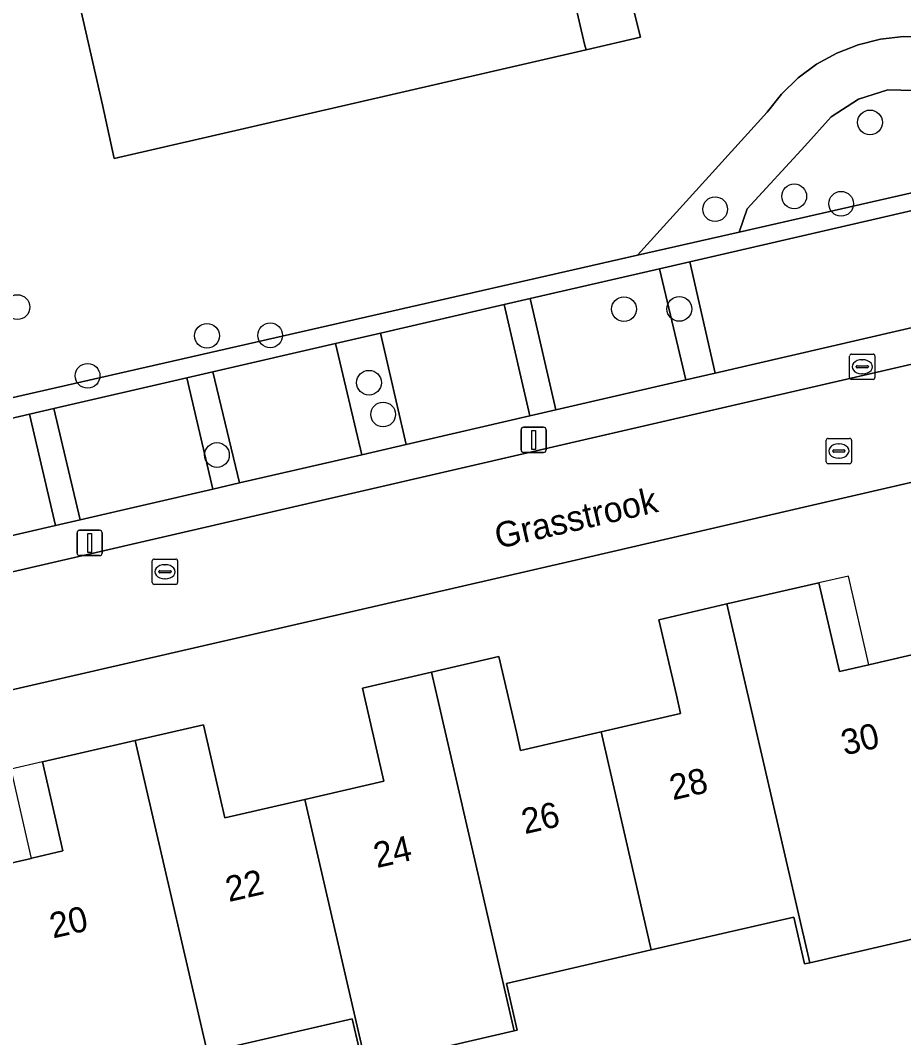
# Model space of a CAD drawing. Extents: x 156412 to 157779, y 382335 to 383768.
# Drawn here: x 156810.03 to 156844.92, y 382698.63 to 382738.81 of the extents above; entities that cross this region are included whole.
import ezdxf

# ---------------------------------------------------------------- set-up
doc = ezdxf.new("R2010")
doc.units = 0
for name, color, linetype in [('IMGEO_Boom', 7, 'Continuous'), ('IMGEO_Brandkraan', 7, 'Continuous'), ('IMGEO_Erf', 7, 'Continuous'), ('IMGEO_Groenvoorziening', 7, 'Continuous'), ('IMGEO_Haag', 7, 'Continuous'), ('IMGEO_Lichtmast', 7, 'Continuous'), ('IMGEO_Openbare_ruimte_label', 7, 'Continuous'), ('IMGEO_Pand', 7, 'Continuous'), ('IMGEO_Pand_nummerreeks', 7, 'Continuous'), ('IMGEO_Pand_overbouw', 7, 'Continuous'), ('IMGEO_Parkeervlak_open', 7, 'Continuous'), ('IMGEO_Rijbaan_lokaal_open', 7, 'Continuous'), ('IMGEO_Rioolput', 7, 'Continuous'), ('IMGEO_Voetpad_gesloten', 7, 'Continuous'), ('IMGEO_Voetpad_open', 7, 'Continuous')]:
    doc.layers.add(name, color=color, linetype=linetype)

msp = doc.modelspace()

# ---------------------------------------------------------------- linework, layer by layer
at = {"layer": 'IMGEO_Boom'}
for centre in [(156843.589, 382734.775), (156840.596, 382731.858), (156842.449, 382731.563), (156837.473, 382731.349), (156809.918, 382727.482), (156833.872, 382727.402), (156836.059, 382727.412), (156817.404, 382726.349), (156819.9, 382726.367), (156812.688, 382724.769), (156823.804, 382724.497), (156824.361, 382723.243), (156817.797, 382721.643)]:
    msp.add_circle(centre, 0.489, dxfattribs=at)
at = {"layer": 'IMGEO_Brandkraan'}
for p, q in [((156842.782, 382724.7), (156842.782, 382725.552)), ((156842.857, 382725.626), (156843.709, 382725.626)), ((156843.783, 382725.552), (156843.783, 382724.7)), ((156843.041, 382725.12), (156843.041, 382725.132)), ((156843.479, 382725.083), (156843.081, 382725.083)), ((156843.084, 382725.169), (156843.482, 382725.169)), ((156843.27, 382725.406), (156843.295, 382725.406)), ((156843.525, 382725.132), (156843.525, 382725.12)), ((156843.293, 382724.846), (156843.268, 382724.846)), ((156843.709, 382724.626), (156842.857, 382724.626))]:
    msp.add_line(p, q, dxfattribs=at)
for points in [[(156842.782, 382724.7), (156842.782, 382725.552)], [(156842.857, 382725.626), (156843.709, 382725.626)], [(156843.783, 382725.552), (156843.783, 382724.7)], [(156843.709, 382724.626), (156842.857, 382724.626)]]:
    msp.add_lwpolyline(points, dxfattribs=at)
for centre, radius, start, end in [((156842.859, 382725.55), 0.0765, 91.552, 178.448), ((156842.859, 382725.55), 0.0765, 91.552, 178.448), ((156843.707, 382725.55), 0.0765, 1.552, 88.448), ((156843.707, 382725.55), 0.0765, 1.552, 88.448), ((156843.081, 382725.129), 0.0403, 85.8775, 175.7526), ((156843.078, 382725.119), 0.0366, 178.938, 274.7102), ((156843.482, 382725.126), 0.043, 264.8664, 352.4533), ((156843.486, 382725.131), 0.0386, 1.7309, 96.639), ((156842.859, 382724.702), 0.0765, 181.552, 268.448), ((156842.859, 382724.702), 0.0765, 181.552, 268.448), ((156843.707, 382724.702), 0.0765, 271.552, 358.448), ((156843.707, 382724.702), 0.0765, 271.552, 358.448)]:
    msp.add_arc(centre, radius, start, end, dxfattribs=at)
for centre, major_axis, ratio, start_param, end_param in [((156843.269, 382725.126), (-0.387, 0.002), 0.722429, 4.712389, 7.853982), ((156843.294, 382725.126), (-0.39, 0.002), 0.717154, 1.570796, 4.712389)]:
    msp.add_ellipse(centre, major_axis=major_axis, ratio=ratio, start_param=start_param, end_param=end_param, dxfattribs=at)
at = {"layer": 'IMGEO_Erf'}
for points in [[(156876.422, 382727.751), (156841.152, 382719.616), (156831.783, 382717.455), (156805.847, 382711.483)], [(156807.399, 382705.016), (156810.455, 382705.715), (156810.491, 382705.723), (156811.711, 382706.017), (156810.912, 382709.528), (156814.572, 382710.371), (156817.265, 382710.992), (156817.952, 382707.999), (156818.109, 382707.317), (156821.274, 382708.044), (156824.389, 382708.76), (156824.231, 382709.449), (156823.544, 382712.434), (156826.272, 382713.065), (156828.935, 382713.681), (156829.625, 382710.694), (156829.791, 382709.976), (156832.969, 382710.71), (156836.111, 382711.436), (156835.945, 382712.154), (156835.254, 382715.14), (156837.941, 382715.759), (156841.57, 382716.594), (156842.378, 382713.092), (156843.549, 382713.362), (156843.595, 382713.373), (156846.542, 382714.052)], [(156864.577, 382697.612), (156870.42, 382698.958), (156876.264, 382700.304), (156882.409, 382701.719), (156880.384, 382710.605), (156874.327, 382709.228), (156874.118, 382709.18), (156868.691, 382707.929), (156868.487, 382707.882), (156862.64, 382706.533), (156856.797, 382705.186), (156849.001, 382703.388), (156841.209, 382701.59), (156841.004, 382701.543), (156840.577, 382703.394), (156834.95, 382702.096), (156829.228, 382700.776), (156829.655, 382698.925), (156829.537, 382698.898), (156823.693, 382697.55)], [(156823.566, 382697.521), (156823.139, 382699.372), (156817.605, 382698.095)]]:
    msp.add_lwpolyline(points, dxfattribs=at)
at = {"layer": 'IMGEO_Groenvoorziening'}
for points in [[(156846.252, 382756.171), (156841.91, 382755.169), (156841.976, 382754.824), (156834.315, 382753.052), (156834.992, 382750.11), (156834.518, 382750), (156831.699, 382749.347), (156834.527, 382738.137), (156832.373, 382737.642), (156813.741, 382733.355), (156813.271, 382735.473), (156811.203, 382744.597), (156813.35, 382745.095), (156812.67, 382748.044), (156812.585, 382748.399), (156807.635, 382747.256)], [(156807.895, 382722.68), (156810.39, 382723.256), (156811.357, 382723.479), (156816.603, 382724.689), (156817.631, 382724.926), (156822.477, 382726.044), (156824.257, 382726.454), (156829.139, 382727.58), (156830.166, 382727.817), (156835.281, 382728.996), (156836.467, 382729.27), (156852.619, 382732.995), (156861.974, 382735.153), (156866.967, 382736.304), (156867.964, 382736.534), (156873.043, 382737.705), (156874.143, 382737.959), (156874.007, 382738.543), (156855.67, 382734.37), (156851.757, 382733.48), (156838.419, 382730.444), (156834.402, 382729.53), (156803.492, 382722.496)], [(156803.492, 382722.496), (156834.402, 382729.53), (156839.533, 382735.185), (156840.097, 382735.898), (156840.749, 382736.531), (156841.48, 382737.073), (156842.275, 382737.513), (156843.121, 382737.845), (156844.003, 382738.064), (156844.907, 382738.164), (156845.816, 382738.144)], [(156845.816, 382738.144), (156844.907, 382738.164), (156844.003, 382738.064), (156843.121, 382737.845), (156842.275, 382737.513), (156841.48, 382737.073), (156840.749, 382736.531), (156840.097, 382735.898), (156839.533, 382735.185), (156834.402, 382729.53), (156838.419, 382730.444), (156838.743, 382731.368), (156841.016, 382733.843), (156842.055, 382734.993), (156843.134, 382735.688), (156844.293, 382736.057), (156846.338, 382736.012)]]:
    msp.add_lwpolyline(points, dxfattribs=at)
msp.add_lwpolyline([(156838.419, 382730.444), (156851.757, 382733.48), (156850.757, 382734.347), (156847.941, 382735.353), (156847.577, 382735.558), (156846.338, 382736.012), (156844.293, 382736.057), (156843.134, 382735.688), (156842.055, 382734.993), (156841.016, 382733.843), (156838.743, 382731.368)], close=True, dxfattribs=at)
at = {"layer": 'IMGEO_Haag'}
msp.add_lwpolyline([(156807.895, 382722.68), (156810.39, 382723.256), (156811.357, 382723.479), (156816.603, 382724.689), (156817.631, 382724.926), (156822.477, 382726.044), (156824.257, 382726.454), (156829.139, 382727.58), (156830.166, 382727.817), (156835.281, 382728.996), (156836.467, 382729.27), (156852.619, 382732.995), (156861.974, 382735.153), (156866.967, 382736.304), (156867.964, 382736.534), (156873.043, 382737.705), (156874.143, 382737.959), (156874.007, 382738.543), (156855.67, 382734.37), (156851.757, 382733.48), (156838.419, 382730.444), (156834.402, 382729.53), (156803.492, 382722.496)], dxfattribs=at)
at = {"layer": 'IMGEO_Lichtmast'}
for p, q in [((156829.908, 382722.741), (156830.698, 382722.741)), ((156830.698, 382722.741), (156829.908, 382722.741)), ((156829.808, 382721.841), (156829.808, 382722.641)), ((156829.808, 382722.641), (156829.808, 382721.841)), ((156830.798, 382722.641), (156830.798, 382721.841)), ((156830.798, 382721.841), (156830.798, 382722.641)), ((156830.698, 382721.741), (156829.908, 382721.741)), ((156829.908, 382721.741), (156830.698, 382721.741)), ((156812.375, 382718.668), (156813.165, 382718.668)), ((156813.165, 382718.668), (156812.375, 382718.668)), ((156812.275, 382717.768), (156812.275, 382718.568)), ((156812.275, 382718.568), (156812.275, 382717.768)), ((156813.265, 382718.568), (156813.265, 382717.768)), ((156813.265, 382717.768), (156813.265, 382718.568)), ((156813.165, 382717.668), (156812.375, 382717.668)), ((156812.375, 382717.668), (156813.165, 382717.668))]:
    msp.add_line(p, q, dxfattribs=at)
for points in [[(156830.228, 382722.616), (156830.378, 382722.616), (156830.378, 382721.866), (156830.228, 382721.866), (156830.228, 382722.616)], [(156812.695, 382718.543), (156812.845, 382718.543), (156812.845, 382717.793), (156812.695, 382717.793), (156812.695, 382718.543)]]:
    msp.add_lwpolyline(points, dxfattribs=at)
for centre, start, end in [((156829.908, 382722.641), 90, 180), ((156829.908, 382722.641), 90, 180), ((156830.698, 382722.641), 0, 90), ((156830.698, 382722.641), 360, 90), ((156829.908, 382721.841), 180, 270), ((156829.908, 382721.841), 180, 270), ((156830.698, 382721.841), 270, 0), ((156830.698, 382721.841), 270, 0), ((156812.375, 382718.568), 90, 180), ((156812.375, 382718.568), 90, 180), ((156813.165, 382718.568), 0, 90), ((156813.165, 382718.568), 360, 90), ((156812.375, 382717.768), 180, 270), ((156812.375, 382717.768), 180, 270), ((156813.165, 382717.768), 270, 0), ((156813.165, 382717.768), 270, 0)]:
    msp.add_arc(centre, 0.1, start, end, dxfattribs=at)
at = {"layer": 'IMGEO_Pand'}
for points in [[(156818.667, 382746.326), (156813.35, 382745.095), (156811.203, 382744.597), (156813.271, 382735.473), (156813.741, 382733.355), (156832.373, 382737.642), (156832.32, 382737.871), (156829.826, 382748.61), (156829.759, 382748.897), (156819.447, 382746.507)], [(156846.542, 382714.052), (156843.595, 382713.373), (156843.549, 382713.362), (156842.378, 382713.092), (156841.57, 382716.594), (156837.941, 382715.759), (156841.209, 382701.59), (156849.001, 382703.388)], [(156841.209, 382701.59), (156837.941, 382715.759), (156835.254, 382715.14), (156835.945, 382712.154), (156836.111, 382711.436), (156832.969, 382710.71), (156834.95, 382702.096), (156840.577, 382703.394), (156841.004, 382701.543)], [(156829.537, 382698.898), (156829.655, 382698.925), (156829.228, 382700.776), (156834.95, 382702.096), (156832.969, 382710.71), (156829.791, 382709.976), (156829.625, 382710.694), (156828.935, 382713.681), (156826.272, 382713.065)], [(156829.537, 382698.898), (156826.272, 382713.065), (156823.544, 382712.434), (156824.231, 382709.449), (156824.389, 382708.76), (156821.274, 382708.044), (156823.693, 382697.55)], [(156821.274, 382708.044), (156818.109, 382707.317), (156817.952, 382707.999), (156817.265, 382710.992), (156814.572, 382710.371), (156817.84, 382696.2), (156818.032, 382696.244), (156817.605, 382698.095), (156823.139, 382699.372), (156823.566, 382697.521), (156823.693, 382697.55)], [(156814.572, 382710.371), (156810.912, 382709.528), (156811.711, 382706.017), (156810.491, 382705.723), (156810.455, 382705.715), (156807.399, 382705.016), (156809.833, 382694.353), (156810.624, 382690.887), (156818.643, 382692.718), (156817.84, 382696.2)]]:
    msp.add_lwpolyline(points, close=True, dxfattribs=at)
at = {"layer": 'IMGEO_Pand_overbouw'}
for points in [[(156843.549, 382713.362), (156842.741, 382716.863), (156841.57, 382716.594), (156842.378, 382713.092)], [(156809.653, 382709.238), (156810.455, 382705.715), (156810.491, 382705.723), (156811.711, 382706.017), (156810.912, 382709.528)]]:
    msp.add_lwpolyline(points, close=True, dxfattribs=at)
at = {"layer": 'IMGEO_Parkeervlak_open'}
for points in [[(156853.63, 382728.608), (156852.619, 382732.995), (156836.467, 382729.27), (156837.468, 382724.874)], [(156835.281, 382728.996), (156830.166, 382727.817), (156831.175, 382723.421), (156836.315, 382724.608)], [(156829.139, 382727.58), (156824.257, 382726.454), (156825.272, 382722.057), (156830.157, 382723.186)], [(156822.477, 382726.044), (156817.631, 382724.926), (156818.691, 382720.537), (156823.524, 382721.654)], [(156816.603, 382724.689), (156811.357, 382723.479), (156812.391, 382719.082), (156817.63, 382720.292)], [(156810.39, 382723.256), (156807.895, 382722.68), (156808.902, 382718.276), (156811.426, 382718.859)]]:
    msp.add_lwpolyline(points, close=True, dxfattribs=at)
at = {"layer": 'IMGEO_Rijbaan_lokaal_open'}
for points in [[(156954.997, 382755.422), (156950.885, 382751.332), (156949.815, 382749.383), (156929.495, 382744.678), (156907.413, 382739.578), (156879.275, 382733.088), (156868.803, 382730.665), (156830.401, 382721.812), (156805.031, 382715.955), (156791.204, 382712.755), (156730.522, 382698.738), (156728.301, 382699.143), (156722.872, 382699.769)], [(156725.3, 382689.329), (156729.8, 382692.978), (156731.555, 382694.305), (156790.393, 382707.765), (156801.982, 382710.553), (156804.578, 382711.178), (156804.954, 382711.268), (156805.847, 382711.483), (156831.783, 382717.455), (156841.152, 382719.616), (156876.422, 382727.751)]]:
    msp.add_lwpolyline(points, dxfattribs=at)
at = {"layer": 'IMGEO_Rioolput'}
for p, q in [((156841.933, 382722.299), (156842.785, 382722.299)), ((156841.858, 382721.373), (156841.858, 382722.225)), ((156842.346, 382722.079), (156842.371, 382722.079)), ((156842.859, 382722.225), (156842.859, 382721.373)), ((156842.117, 382721.793), (156842.117, 382721.805)), ((156842.555, 382721.756), (156842.157, 382721.756)), ((156842.16, 382721.842), (156842.558, 382721.842)), ((156842.369, 382721.519), (156842.344, 382721.519)), ((156842.601, 382721.805), (156842.601, 382721.793)), ((156842.785, 382721.299), (156841.933, 382721.299)), ((156815.244, 382716.606), (156815.244, 382717.458)), ((156815.319, 382717.532), (156816.171, 382717.532)), ((156816.245, 382717.458), (156816.245, 382716.606)), ((156815.503, 382717.026), (156815.503, 382717.038)), ((156815.546, 382717.075), (156815.944, 382717.075)), ((156815.732, 382717.312), (156815.757, 382717.312)), ((156815.987, 382717.038), (156815.987, 382717.026)), ((156815.941, 382716.989), (156815.543, 382716.989)), ((156815.755, 382716.752), (156815.73, 382716.752)), ((156816.171, 382716.532), (156815.319, 382716.532))]:
    msp.add_line(p, q, dxfattribs=at)
for points in [[(156841.933, 382722.299), (156842.785, 382722.299)], [(156841.858, 382721.373), (156841.858, 382722.225)], [(156842.859, 382722.225), (156842.859, 382721.373)], [(156842.785, 382721.299), (156841.933, 382721.299)], [(156815.244, 382716.606), (156815.244, 382717.458)], [(156815.319, 382717.532), (156816.171, 382717.532)], [(156816.245, 382717.458), (156816.245, 382716.606)], [(156816.171, 382716.532), (156815.319, 382716.532)]]:
    msp.add_lwpolyline(points, dxfattribs=at)
for centre, radius, start, end in [((156841.935, 382722.223), 0.0765, 91.552, 178.448), ((156841.935, 382722.223), 0.0765, 91.552, 178.448), ((156842.783, 382722.223), 0.0765, 1.552, 88.448), ((156842.783, 382722.223), 0.0765, 1.552, 88.448), ((156842.157, 382721.802), 0.0403, 85.8775, 175.7526), ((156842.154, 382721.792), 0.0366, 178.938, 274.7102), ((156842.558, 382721.799), 0.043, 264.8664, 352.4533), ((156842.562, 382721.804), 0.0386, 1.7309, 96.639), ((156841.935, 382721.375), 0.0765, 181.552, 268.448), ((156841.935, 382721.375), 0.0765, 181.552, 268.448), ((156842.783, 382721.375), 0.0765, 271.552, 358.448), ((156842.783, 382721.375), 0.0765, 271.552, 358.448), ((156815.321, 382717.456), 0.0765, 91.552, 178.448), ((156815.321, 382717.456), 0.0765, 91.552, 178.448), ((156816.169, 382717.456), 0.0765, 1.552, 88.448), ((156816.169, 382717.456), 0.0765, 1.552, 88.448), ((156815.543, 382717.035), 0.0403, 85.8775, 175.7526), ((156815.948, 382717.037), 0.0386, 1.7309, 96.639), ((156815.54, 382717.025), 0.0366, 178.938, 274.7102), ((156815.944, 382717.032), 0.043, 264.8664, 352.4533), ((156815.321, 382716.608), 0.0765, 181.552, 268.448), ((156815.321, 382716.608), 0.0765, 181.552, 268.448), ((156816.169, 382716.608), 0.0765, 271.552, 358.448), ((156816.169, 382716.608), 0.0765, 271.552, 358.448)]:
    msp.add_arc(centre, radius, start, end, dxfattribs=at)
for centre, major_axis, ratio, start_param, end_param in [((156842.345, 382721.799), (-0.387, 0.002), 0.722429, 4.712389, 7.853982), ((156842.37, 382721.799), (-0.39, 0.002), 0.717154, 1.570796, 4.712389), ((156815.731, 382717.032), (-0.387, 0.002), 0.722429, 4.712389, 7.853982), ((156815.756, 382717.032), (-0.39, 0.002), 0.717154, 1.570796, 4.712389)]:
    msp.add_ellipse(centre, major_axis=major_axis, ratio=ratio, start_param=start_param, end_param=end_param, dxfattribs=at)
at = {"layer": 'IMGEO_Voetpad_gesloten'}
msp.add_lwpolyline([(156831.699, 382749.347), (156829.759, 382748.897), (156829.826, 382748.61), (156832.32, 382737.871), (156832.373, 382737.642), (156834.527, 382738.137)], close=True, dxfattribs=at)
at = {"layer": 'IMGEO_Voetpad_open'}
for points in [[(156946.378, 382750), (156878.945, 382734.453), (156877.577, 382734.138), (156875.16, 382733.581), (156874.073, 382733.33), (156868.975, 382732.152), (156867.967, 382731.919), (156863.097, 382730.795), (156853.63, 382728.608), (156837.468, 382724.874), (156836.315, 382724.608), (156831.175, 382723.421), (156830.157, 382723.186), (156825.272, 382722.057), (156823.524, 382721.654), (156818.691, 382720.537), (156817.63, 382720.292), (156812.391, 382719.082), (156811.426, 382718.859), (156808.902, 382718.276)], [(156805.031, 382715.955), (156830.401, 382721.812), (156868.803, 382730.665), (156879.275, 382733.088), (156907.413, 382739.578)]]:
    msp.add_lwpolyline(points, dxfattribs=at)
for points in [[(156836.467, 382729.27), (156835.281, 382728.996), (156836.315, 382724.608), (156837.468, 382724.874)], [(156830.166, 382727.817), (156829.139, 382727.58), (156830.157, 382723.186), (156831.175, 382723.421)], [(156824.257, 382726.454), (156822.477, 382726.044), (156823.524, 382721.654), (156825.272, 382722.057)], [(156817.631, 382724.926), (156816.603, 382724.689), (156817.63, 382720.292), (156818.691, 382720.537)], [(156811.357, 382723.479), (156810.39, 382723.256), (156811.426, 382718.859), (156812.391, 382719.082)]]:
    msp.add_lwpolyline(points, close=True, dxfattribs=at)

# ---------------------------------------------------------------- texts
at = {"layer": 'IMGEO_Openbare_ruimte_label'}
msp.add_text('Grasstrook', height=1, rotation=13.0075, dxfattribs=at).set_placement((156828.899, 382717.934))
at = {"layer": 'IMGEO_Pand_nummerreeks'}
for s, rotation, p in [('30', 12.9832, (156842.58, 382709.774)), ('28', 12.9077, (156835.803, 382708.006)), ('26', 12.9077, (156829.956, 382706.666)), ('24', 12.9077, (156824.112, 382705.327)), ('22', 12.9077, (156818.265, 382703.987)), ('20', 12.8801, (156811.321, 382702.548))]:
    msp.add_text(s, height=1, rotation=rotation, dxfattribs=at).set_placement(p)

doc.saveas('drawing.dxf')
